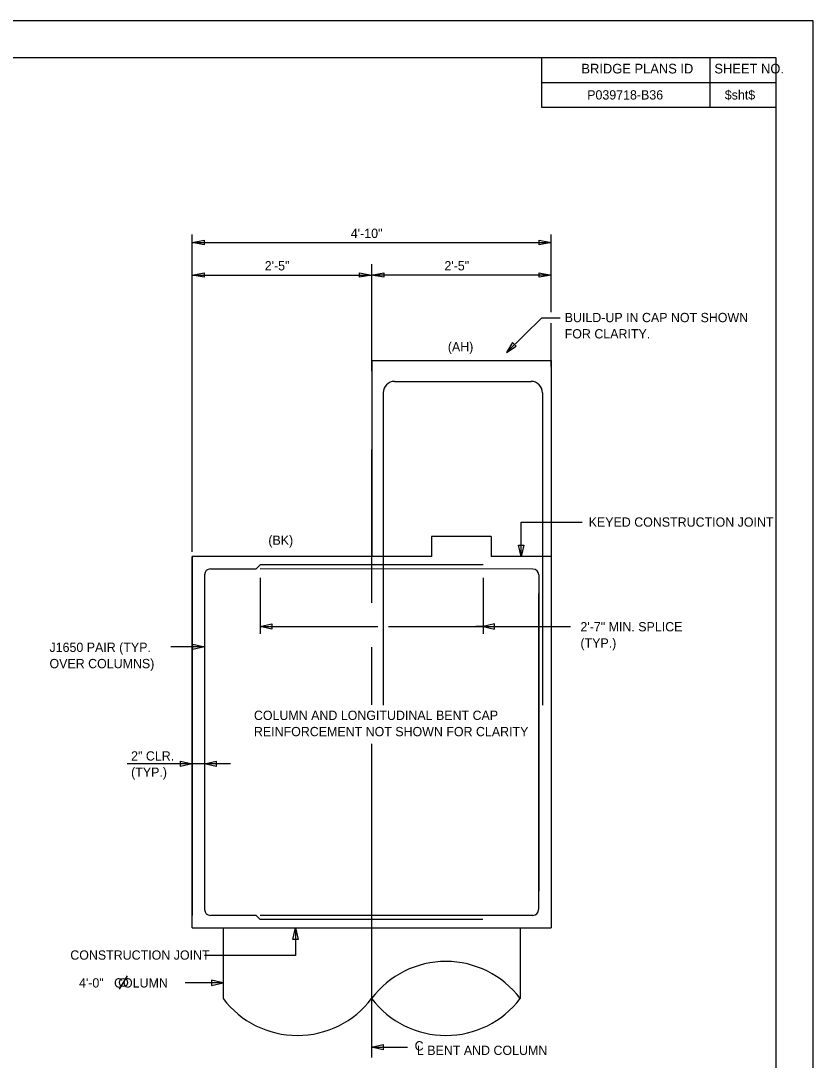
# Model space of a CAD drawing. Extents: x 1970675.2 to 1970711.3, y 796145.2 to 796167.2.
# Drawn here: x 1970700.57 to 1970711.24, y 796153.25 to 796167.25 of the extents above; entities that cross this region are included whole.
import ezdxf

# ---------------------------------------------------------------- set-up
doc = ezdxf.new("R2010")
doc.units = 0
for name, color, linetype in [('BR_AUTO DIMENSION', 7, 'Continuous'), ('BR_BORDER LINES', 7, 'Continuous'), ('BR_CENTER LINES', 7, 'Continuous'), ('BR_CONCRETE', 7, 'Continuous'), ('BR_REBAR', 7, 'Continuous'), ('BR_TEXT', 7, 'Continuous'), ('Level 31', 7, 'Continuous')]:
    doc.layers.add(name, color=color, linetype=linetype)

msp = doc.modelspace()

# ---------------------------------------------------------------- linework, layer by layer
at = {"layer": 'BR_AUTO DIMENSION'}
for p, q in [((1970702.874, 796160.092), (1970702.874, 796164.366)), ((1970707.707, 796163.323), (1970707.707, 796164.367)), ((1970702.874, 796164.259), (1970707.707, 796164.259)), ((1970702.874, 796163.822), (1970705.29, 796163.822)), ((1970707.707, 796163.822), (1970705.29, 796163.822)), ((1970707.707, 796162.592), (1970707.707, 796163.173)), ((1970703.79, 796159.742), (1970703.79, 796158.989)), ((1970706.79, 796159.742), (1970706.79, 796158.989)), ((1970703.79, 796159.086), (1970705.372, 796159.086)), ((1970705.515, 796159.086), (1970707.966, 796159.086)), ((1970703.04, 796158.814), (1970702.586, 796158.814)), ((1970703.391, 796157.237), (1970701.999, 796157.237)), ((1970704.263, 796155.029), (1970704.263, 796154.657)), ((1970704.263, 796154.657), (1970703.04, 796154.657)), ((1970703.29, 796154.288), (1970702.778, 796154.288)), ((1970705.29, 796153.422), (1970705.773, 796153.422))]:
    msp.add_line(p, q, dxfattribs=at)
for points in [[(1970703.036, 796164.227), (1970702.874, 796164.259), (1970703.036, 796164.29)], [(1970707.545, 796164.29), (1970707.707, 796164.259), (1970707.545, 796164.228)], [(1970703.036, 796163.791), (1970702.874, 796163.822), (1970703.036, 796163.853)], [(1970705.128, 796163.853), (1970705.29, 796163.822), (1970705.128, 796163.791)], [(1970705.453, 796163.791), (1970705.29, 796163.822), (1970705.453, 796163.853)], [(1970707.545, 796163.853), (1970707.707, 796163.822), (1970707.545, 796163.791)], [(1970707.186, 796162.915), (1970707.104, 796162.777), (1970707.238, 796162.865)], [(1970707.34, 796160.185), (1970707.304, 796160.029), (1970707.268, 796160.185)], [(1970703.946, 796159.05), (1970703.79, 796159.086), (1970703.946, 796159.122)], [(1970706.946, 796159.122), (1970706.79, 796159.086), (1970706.946, 796159.05)], [(1970702.884, 796158.85), (1970703.04, 796158.814), (1970702.884, 796158.778)], [(1970702.717, 796157.273), (1970702.873, 796157.237), (1970702.717, 796157.201)], [(1970703.196, 796157.201), (1970703.04, 796157.237), (1970703.196, 796157.273)], [(1970704.227, 796154.873), (1970704.263, 796155.029), (1970704.299, 796154.873)], [(1970703.134, 796154.252), (1970703.29, 796154.288), (1970703.134, 796154.324)], [(1970705.446, 796153.386), (1970705.29, 796153.422), (1970705.446, 796153.458)]]:
    msp.add_lwpolyline(points, close=True, dxfattribs=at)
for points in [[(1970707.104, 796162.778), (1970707.584, 796163.245), (1970707.828, 796163.245)], [(1970707.304, 796160.029), (1970707.304, 796160.492), (1970708.125, 796160.492)]]:
    msp.add_lwpolyline(points, dxfattribs=at)
at = {"layer": 'BR_BORDER LINES'}
for p, q in [((1970710.736, 796166.746), (1970677.07, 796166.746)), ((1970707.584, 796166.08), (1970707.584, 796166.746)), ((1970709.85, 796166.08), (1970709.85, 796166.746)), ((1970710.736, 796145.746), (1970710.736, 796166.746)), ((1970707.584, 796166.417), (1970710.736, 796166.417)), ((1970709.85, 796166.417), (1970710.736, 796166.417)), ((1970710.736, 796166.08), (1970707.584, 796166.08))]:
    msp.add_line(p, q, dxfattribs=at)
at = {"layer": 'BR_CENTER LINES'}
for p, q in [((1970705.29, 796163.97), (1970705.29, 796162.529)), ((1970705.29, 796161.47), (1970705.29, 796159.406)), ((1970705.29, 796158.811), (1970705.29, 796158.033)), ((1970705.29, 796157.509), (1970705.29, 796153.282))]:
    msp.add_line(p, q, dxfattribs=at)
at = {"layer": 'BR_CONCRETE'}
for p, q in [((1970705.291, 796162.67), (1970705.291, 796160.029)), ((1970705.291, 796162.67), (1970707.707, 796162.67)), ((1970707.707, 796162.67), (1970707.707, 796160.029)), ((1970706.901, 796160.298), (1970706.096, 796160.298)), ((1970706.096, 796160.298), (1970706.096, 796160.029)), ((1970706.901, 796160.298), (1970706.901, 796160.029)), ((1970702.874, 796160.029), (1970702.874, 796155.196)), ((1970702.874, 796155.029), (1970702.874, 796160.029)), ((1970705.29, 796160.029), (1970702.874, 796160.029)), ((1970706.096, 796160.029), (1970705.29, 796160.029)), ((1970707.707, 796160.029), (1970706.901, 796160.029)), ((1970707.707, 796160.029), (1970707.707, 796155.029)), ((1970702.873, 796155.029), (1970703.29, 796155.029)), ((1970703.29, 796155.029), (1970707.29, 796155.029)), ((1970703.29, 796155.029), (1970703.29, 796154.078)), ((1970707.29, 796155.029), (1970707.706, 796155.029)), ((1970707.29, 796155.029), (1970707.29, 796154.078))]:
    msp.add_line(p, q, dxfattribs=at)
for centre, start, end in [((1970706.29, 796153.324), 37.0023, 142.9977), ((1970704.29, 796154.831), 217.0023, 322.9977), ((1970706.29, 796154.831), 217.0023, 322.9977)]:
    msp.add_arc(centre, 1.252, start, end, dxfattribs=at)
at = {"layer": 'BR_REBAR'}
for p, q in [((1970705.599, 796162.39), (1970707.437, 796162.39)), ((1970705.445, 796162.237), (1970705.445, 796158.029)), ((1970707.591, 796162.237), (1970707.591, 796158.029)), ((1970703.118, 796159.863), (1970703.735, 796159.863)), ((1970703.735, 796159.863), (1970703.79, 796159.918)), ((1970706.79, 796159.918), (1970703.79, 796159.918)), ((1970707.462, 796159.862), (1970703.79, 796159.863)), ((1970703.04, 796159.785), (1970703.039, 796155.275)), ((1970707.54, 796159.784), (1970707.54, 796155.524)), ((1970707.539, 796159.534), (1970707.539, 796155.274)), ((1970703.734, 796155.196), (1970703.118, 796155.197)), ((1970703.734, 796155.196), (1970703.789, 796155.141)), ((1970707.461, 796155.196), (1970703.789, 796155.196)), ((1970706.789, 796155.141), (1970703.789, 796155.141))]:
    msp.add_line(p, q, dxfattribs=at)
for centre, radius, start, end in [((1970705.601, 796162.234), 0.156, 91.025, 178.975), ((1970707.435, 796162.234), 0.156, 1.025, 88.975), ((1970703.118, 796159.785), 0.0781, 90, 180), ((1970707.462, 796159.784), 0.0781, 360, 90), ((1970703.118, 796155.275), 0.0781, 180, 270), ((1970707.461, 796155.274), 0.0781, 270, 360)]:
    msp.add_arc(centre, radius, start, end, dxfattribs=at)
at = {"layer": 'BR_TEXT'}
for p, q in [((1970703.79, 796159.086), (1970703.868, 796159.086)), ((1970706.79, 796159.086), (1970706.693, 796159.086)), ((1970701.896, 796154.201), (1970702.001, 796154.382))]:
    msp.add_line(p, q, dxfattribs=at)
msp.add_circle((1970701.949, 796154.292), 0.055, dxfattribs=at)
at = {"layer": 'Level 31'}
msp.add_lwpolyline([(1970675.236, 796145.246), (1970711.236, 796145.246), (1970711.236, 796167.246), (1970675.236, 796167.246)], close=True, dxfattribs=at)

# ---------------------------------------------------------------- texts
at = {"layer": 'BR_AUTO DIMENSION'}
for s, p in [('4\'-10"', (1970705.01, 796164.321)), ('2\'-5"', (1970703.85, 796163.884)), ('2\'-5"', (1970706.27, 796163.884)), ('(AH)', (1970706.316, 796162.794)), ('(BK)', (1970703.899, 796160.188))]:
    msp.add_text(s, height=0.125, dxfattribs=at).set_placement(p)
at = {"layer": 'BR_TEXT'}
for s, height, p in [('BRIDGE PLANS ID', 0.13, (1970708.115, 796166.537)), ('SHEET NO.', 0.13, (1970709.906, 796166.537)), ('P039718-B36', 0.125, (1970708.193, 796166.186)), ('$sht$', 0.125, (1970710.046, 796166.186)), ('KEYED CONSTRUCTION JOINT', 0.125, (1970708.213, 796160.432))]:
    msp.add_text(s, height=height, dxfattribs=at).set_placement(p)
for s, p in [('BUILD-UP IN CAP NOT SHOWN', (1970707.89, 796163.187)), ('FOR CLARITY.', (1970707.89, 796162.968)), ('2\'-7" MIN. SPLICE', (1970708.102, 796159.022)), ('J1650 PAIR (TYP.', (1970700.952, 796158.745)), ('(TYP.)', (1970708.102, 796158.803)), ('OVER COLUMNS)', (1970700.952, 796158.526)), ('COLUMN AND LONGITUDINAL BENT CAP', (1970703.705, 796157.829)), ('REINFORCEMENT NOT SHOWN FOR CLARITY', (1970703.705, 796157.61)), ('2" CLR.', (1970702.051, 796157.282)), ('(TYP.)', (1970702.051, 796157.063)), ('CONSTRUCTION JOINT', (1970701.232, 796154.6)), ('4\'-0"   COLUMN', (1970701.349, 796154.225)), ('C', (1970705.869, 796153.377)), ('L BENT AND COLUMN', (1970705.9, 796153.317))]:
    msp.add_text(s, height=0.125, rotation=360, dxfattribs=at).set_placement(p)

doc.saveas('drawing.dxf')
